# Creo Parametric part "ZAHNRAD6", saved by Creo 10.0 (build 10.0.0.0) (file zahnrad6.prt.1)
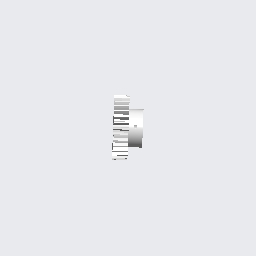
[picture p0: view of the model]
Units: millimeter Newton Second (mmNs); MM, TONNE, SECS

Created from: 29603200.PRT

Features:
  1. coordinate system "29603200"
  2. imported feature "Import-ke ID 5"
  3. datum axis "A_1"
  4. datum axis "A_2"
  5. datum plane "DTM1"
  6. datum plane "DTM2"
  7. datum plane "DTM3"
  8. datum plane "DEFAULT_1"
  9. cut
  10. datum axis "A_4"
  11. datum axis "A_5"
  12. hole "Bohrung 1"

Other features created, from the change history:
  feature "Baugruppenmaterialschnitt ID 1107296256"
  extruded cut "Profil 1"
  datum axis "A_1"
  datum axis "A_2"

Other named items: NOTE_0

Notes: 29603200

Surfaces: 131 plane, 69 cylinder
